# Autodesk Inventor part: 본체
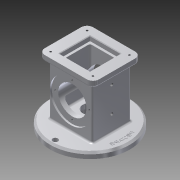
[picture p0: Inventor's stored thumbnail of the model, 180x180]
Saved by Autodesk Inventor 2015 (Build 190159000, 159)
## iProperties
Created: 2019-08
Part Number: 본체
Material: 알루미늄 6061
Document SubType Name: Modeling
Designer: CAD-08
Density: 2.7 g/cm^3
Appearance: 알루미늄 - 평지
Mass: 1038.82 g
Surface Area: 783.569 cm^2
Volume: 384.748 cm^3
Author: CAD-08
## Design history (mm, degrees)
sketch "스케치1"
  geometry: C1 r 67.5 at (0, 0); 1 further point
  constraints: 1 centre point, 1 coincident
  dimensions: "d0" = 135 diameter of C1
extrude "돌출1" new body sketch "스케치1" distance "d1" = 10; taper "d2" = 0 deg
sketch "스케치2"
  geometry: L1 (-37, 33)-(37, 33); L2 (37, 33)-(37, -33); L3 (37, -33)-(-37, -33); L4 (-37, -33)-(-37, 33); L5 (-37, 33)-(37, -33); L6 (37, 33)-(-37, -33); C1 r 67.5 at (0, 0) reference
  constraints: 12 end point, 2 midpoint, 2 parallel, 1 horizontal, 1 perpendicular
  dimensions: "d3" = 66 distance of L1.end L2.end; "d4" = 74 distance of L1.start L1.end
extrude "돌출2" join sketch "스케치2" distance "d5" = 88; taper "d6" = 0 deg
sketch "스케치3"
  geometry: L1 (-46, 41)-(46, 41); L2 (46, 41)-(46, -41); L3 (46, -41)-(-46, -41); L4 (-46, -41)-(-46, 41); L5 (-46, 41)-(46, -41); L6 (46, 41)-(-46, -41); 1 further point
  constraints: 12 end point, 2 midpoint, 2 parallel, 1 horizontal, 1 perpendicular
  dimensions: "d7" = 92 distance of L2.end L3.end; "d8" = 82 distance of L1.end L2.end
extrude "돌출3" join sketch "스케치3" distance "d9" = 10; taper "d10" = 0 deg
chamfer "모따기1" distance "d11" = 3; stored, may be unused: second distance "d12" = 2, angle "d13" = 45 deg
sketch "스케치4"
  geometry: L1 (-26, 26)-(26, 26); L2 (26, 26)-(26, -26); L3 (26, -26)-(-26, -26); L4 (-26, -26)-(-26, 26); L5 (-26, 26)-(26, -26); L6 (26, 26)-(-26, -26); 1 further point
  constraints: 12 end point, 2 midpoint, 2 parallel, 1 horizontal, 1 perpendicular
  dimensions: "d16" = 52 distance of L2.end L3.end; "d17" = 52 distance of L1.end L2.end
extrude "돌출4" cut sketch "스케치4" distance "d18" = 8; taper "d19" = 0 deg
sketch "스케치5"
  geometry: L1 (-22, 22)-(22, 22); L2 (22, 22)-(22, -22); L3 (22, -22)-(-22, -22); L4 (-22, -22)-(-22, 22); L5 (-22, 22)-(22, -22); L6 (22, 22)-(-22, -22); 1 further point
  constraints: 12 end point, 2 midpoint, 2 parallel, 1 horizontal, 1 perpendicular
  dimensions: "d20" = 44 distance of L2.end L3.end; "d21" = 44 distance of L3.end L1.start
extrude "돌출5" cut sketch "스케치5" distance "d22" = 74; taper "d23" = 0 deg
sketch "스케치6"
  geometry: C1 r 67.5 at (0, 0) reference
hole "구멍1" sketch "스케치6" at (0, 0) diameter "d24" = 25; stored, may be unused: countersink angle "d28" = 90 deg, drill point angle "d30" = 0 deg; dims "d25" = 6, "d26" = 50, "d27" = 18, "d29" = 50
fillet "모깎기3" dims "d31" = 10
fillet "모깎기4" dims "d32" = 3
fillet "모깎기5" dims "d33" = 3
sketch "스케치9"
  geometry: A1 r 10 centre (36, 31) between (46, 31) and (36, 41) reference; A2 r 10 centre (-36, 31) between (-36, 41) and (-46, 31) reference; A3 r 10 centre (-36, -31) between (-46, -31) and (-36, -41) reference; A4 r 10 centre (36, -31) between (36, -41) and (46, -31) reference; 1 further point
hole "구멍4" sketch "스케치9" at (36, -31), (36, 31), (-36, 31), (-36, -31) diameter "d53" = 3.242; stored, may be unused: countersink angle "d57" = 90 deg, drill point angle "d59" = 118 deg; dims "d54" = 4, "d55" = 70, "d56" = 3, "d58" = 6
fillet "모깎기6" dims "d69" = 3
sketch "스케치11"
  geometry: C1 r 64.5 at (0, 0) reference; C2 r 59 at (0, 0)
  constraints: 1 centre point, 1 coincident, 1 other
  dimensions: "d70" = 118 diameter of C2
feature "엠보싱1" sketch "스케치11" dims "d2" = 0, "d10" = 0, "d71" = 0.5, "d72" = 0
chamfer "모따기2" distance "d73" = 1; stored, may be unused: second distance "d74" = 2, angle "d75" = 45 deg
fillet "모깎기7" dims "d76" = 3
fillet "모깎기9" dims "d78" = 3
fillet "모깎기10" dims "d79" = 3
sketch "스케치12"
  geometry: C1 r 64.5 at (0, 0) reference; A1 r 59 centre (0, 0) between (-59, 0) and (0, 59); 1 further point
  constraints: 3 point on circle, 2 vertical alignment, 1 centre point, 1 coincident, 1 horizontal alignment
  dimensions: "d80" = 118 diameter of A1
hole "구멍6" sketch "스케치12" at (-59, 0), (0, 59), (0, -59) diameter "d81" = 9; stored, may be unused: countersink angle "d85" = 90 deg, drill point angle "d87" = 0 deg; dims "d82" = 12, "d83" = 70, "d84" = 3, "d86" = 30
fillet "모깎기11" dims "d88" = 3
sketch "스케치13"
  geometry: L1 (-33.5, -95)-(101.5, -95) reference; 2 further points
  constraints: 1 vertical alignment
  dimensions: "d89" = 54 distance from line of L1 point (34, -41)
hole "구멍7" sketch "스케치13" at (34, -41) diameter "d90" = 48; stored, may be unused: countersink angle "d94" = 90 deg, drill point angle "d96" = 0 deg; dims "d91" = 12, "d92" = 70, "d93" = 3, "d95" = 30
sketch "스케치14"
  geometry: L1 (95, -37.5)-(95, 97.5) reference; 4 further points
  constraints: 2 horizontal alignment, 1 midpoint
  dimensions: "d97" = 37 distance from line of L1 point (58, 30); "d98" = 43 distance of point (58, 30) point (15, 30)
hole "구멍8" sketch "스케치14" at (15, 30), (58, 30) diameter "d99" = 4.917; stored, may be unused: countersink angle "d103" = 90 deg, drill point angle "d105" = 0 deg; dims "d100" = 12, "d101" = 70, "d102" = 3, "d104" = 30
sketch "스케치15"
  geometry: C1 r 35 at (0, 0) reference; 2 further points
  constraints: 1 vertical alignment
  dimensions: "d106" = 29 distance of C1.centre point (0, 29)
hole "구멍9" sketch "스케치15" at (0, 29) diameter "d107" = 3.242; stored, may be unused: countersink angle "d111" = 90 deg, drill point angle "d113" = 118 deg; dims "d108" = 4, "d109" = 70, "d110" = 3, "d112" = 6
node "솔리드1"
mirror "대칭3"
pattern_circular "원형 패턴2" dims angle "d115" = 360 deg
mirror "대칭4"
